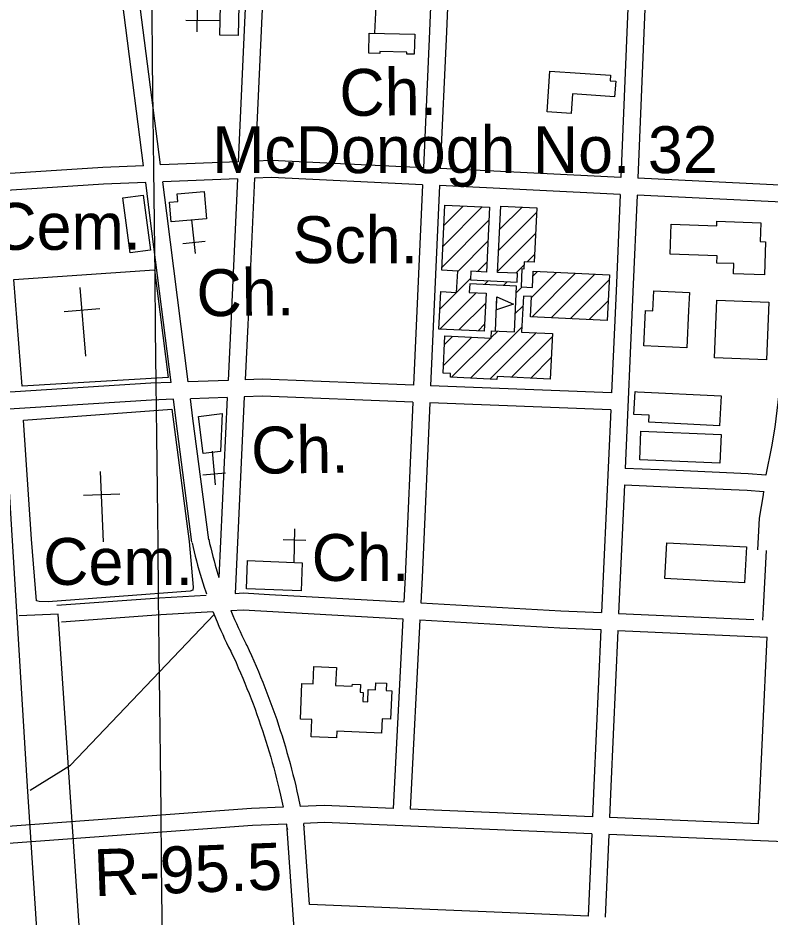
# Model space of a CAD drawing. Extents: x 3677843 to 3715951, y 511991 to 537744.
# Drawn here: x 3687026 to 3688357, y 526272 to 527864 of the extents above; entities that cross this region are included whole.
import ezdxf

# ---------------------------------------------------------------- set-up
doc = ezdxf.new("R2010")
doc.units = 0
for name, color, linetype in [('V-BLDG-IDEN', 7, 'Continuous'), ('V-BLDG-OTLN', 7, 'Continuous'), ('V-GRID-MAJR', 7, 'Continuous'), ('V-RIVR-RANG-IDEN', 7, 'Continuous'), ('V-ROAD-CNTR', 7, 'Continuous'), ('V-SITE-OTLN', 7, 'Continuous'), ('V-SITE-OTLN-IDEN', 7, 'Continuous')]:
    doc.layers.add(name, color=color, linetype=linetype)

msp = doc.modelspace()

# ---------------------------------------------------------------- linework, layer by layer
at = {"layer": 'V-BLDG-OTLN'}
for p, q in [((3687778.4752784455, 527459.874870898), (3687847.7878484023, 527529.1874408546)), ((3687780.2604947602, 527497.015426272), (3687814.0541724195, 527530.8091039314)), ((3687876.864537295, 527452.1981125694), (3687943.984850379, 527519.3184256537)), ((3687878.6501828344, 527489.339097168), (3687918.3094837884, 527528.9983981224)), ((3687776.690062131, 527422.7343155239), (3687859.613205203, 527505.6574585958)), ((3687804.3940204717, 527415.0829348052), (3687857.8268622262, 527468.5157765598)), ((3687875.078891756, 527415.057127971), (3687942.1988848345, 527482.1771210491)), ((3687927.2875798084, 527431.9104769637), (3687940.4129192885, 527445.0358164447)), ((3687839.327857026, 527414.6614323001), (3687856.04051925, 527431.3740945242)), ((3687907.16133071, 527411.7842278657), (3687921.991344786, 527426.6142419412)), ((3687935.1778677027, 527369.09008674), (3687979.387713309, 527413.2999323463)), ((3687936.0287458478, 527334.5856258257), (3688013.1207060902, 527411.6775860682)), ((3687937.582053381, 527406.8496114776), (3687945.6547205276, 527414.922278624)), ((3687969.762257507, 527332.9637984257), (3688046.8536988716, 527410.0552397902)), ((3687802.608089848, 527377.9416651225), (3687826.990631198, 527402.3242064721)), ((3687851.625244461, 527391.603480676), (3687858.484113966, 527398.4623501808)), ((3687885.358267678, 527389.9811648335), (3687892.217521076, 527396.8404182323)), ((3688003.4957691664, 527331.3419710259), (3688072.396078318, 527400.2422801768)), ((3687772.875313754, 527348.2088890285), (3687802.5864146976, 527377.9199899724)), ((3687772.986086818, 527312.9643230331), (3687837.128189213, 527377.1064254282)), ((3687908.097118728, 527377.3646768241), (3687918.292884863, 527387.5604429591)), ((3687806.7180800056, 527311.3409771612), (3687853.867621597, 527358.4905187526)), ((3687871.396575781, 527309.963218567), (3687873.7355711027, 527369.9170986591)), ((3688037.2292808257, 527329.720143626), (3688070.609743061, 527363.1006058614)), ((3687906.310906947, 527340.2231259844), (3687919.782329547, 527353.6945485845)), ((3687827.3458372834, 527225.9027172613), (3687917.9956583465, 527316.5525383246)), ((3687840.450073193, 527309.7176312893), (3687852.0818306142, 527321.3493887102)), ((3687863.9145900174, 527297.8268090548), (3687875.4122137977, 527309.3244328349)), ((3687779.2358858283, 527248.5034439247), (3687829.1952836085, 527298.4628417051)), ((3687781.0219190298, 527285.6448161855), (3687795.461775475, 527300.0846726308)), ((3687793.6122612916, 527227.5244803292), (3687862.9287917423, 527296.8410107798)), ((3687861.0794132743, 527224.2809541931), (3687943.2467605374, 527306.4483014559)), ((3687899.8535028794, 527227.6997047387), (3687971.642557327, 527299.4887591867)), ((3687933.586616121, 527226.0774789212), (3687969.8561386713, 527262.3470014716)), ((3687967.3197293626, 527224.4552531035), (3687968.0697200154, 527225.2052437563))]:
    msp.add_line(p, q, dxfattribs=at)
for points in [[(3687383.756, 527833.48), (3687386.173, 527940.468), (3687418.228, 527939.745), (3687415.807, 527832.755)], [(3687647.903, 527836.958), (3687728.529, 527834.987), (3687727.662, 527799.426), (3687714.43, 527799.748), (3687714.5160000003, 527803.203), (3687666.614, 527804.372), (3687666.522, 527800.604), (3687647.025, 527801.085)], [(3688007.518, 527729.1630000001), (3688005.144, 527694.626), (3687962.582, 527697.552), (3687967.534, 527769.601), (3688075.1040000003, 527762.208), (3688074.4280000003, 527752.373), (3688084.058, 527751.712), (3688082.1550000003, 527724.033)], [(3687248.193, 527549.808), (3687260.958, 527452.693), (3687224.895, 527447.952), (3687212.128, 527545.066)], [(3687355.785, 527556.425), (3687359.737, 527507.844), (3687297.615, 527502.792), (3687294.771, 527537.759), (3687309.348, 527538.9450000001), (3687308.259, 527552.558)], [(3687851.497, 527309.186), (3687771.185, 527313.051), (3687774.369, 527379.277), (3687802.6070000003, 527377.919), (3687804.426, 527415.748), (3687776.419, 527417.095), (3687781.9590000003, 527532.352), (3687860.715, 527528.566), (3687855.2, 527413.898), (3687827.611, 527415.225), (3687826.878, 527399.982), (3687909.468, 527396.011), (3687910.219, 527411.637), (3687874.9960000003, 527413.333), (3687880.644, 527530.81), (3687944.39, 527527.7440000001), (3687939.753, 527431.312), (3687922.257, 527432.152), (3687921.6350000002, 527419.186), (3687918.02, 527419.358), (3687916.4960000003, 527387.647), (3687936.612, 527386.678), (3687937.988, 527415.291), (3688072.808, 527408.807), (3688068.931, 527328.196), (3687933.525, 527334.706), (3687935.238, 527370.341), (3687920.617, 527371.046), (3687917.569, 527307.683), (3687971.911, 527305.0700000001), (3687968.032, 527224.421), (3687874, 527228.943), (3687873.7460000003, 527223.672), (3687791.667, 527227.618), (3687791.9820000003, 527234.2170000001), (3687778.58, 527234.8640000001), (3687781.748, 527300.7440000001), (3687863.865, 527296.796), (3687864.4930000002, 527309.85), (3687904.757, 527307.912), (3687908.65, 527388.861), (3687825.727, 527392.849), (3687824.998, 527377.6900000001), (3687854.722, 527376.26)], [(3688182.033597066, 527498.500976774), (3688262.6984357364, 527495.84298209), (3688262.9614352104, 527503.82796612), (3688340.835279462, 527501.2689712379), (3688339.735281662, 527467.8000381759), (3688349.15626282, 527467.490038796), (3688347.232266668, 527408.8621560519), (3688292.704375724, 527410.651152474), (3688293.2993745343, 527428.7711162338), (3688262.9734351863, 527429.766114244), (3688263.3954343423, 527442.6280885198), (3688180.2866005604, 527445.35808306)], [(3688213.0235350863, 527346.0432816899), (3688209.8095415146, 527279.5784146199), (3688133.7416936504, 527283.256407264), (3688136.760687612, 527345.6882823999), (3688149.962661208, 527345.0502836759), (3688151.679657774, 527380.574212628), (3688214.545532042, 527377.5352187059)], [(3687873.7355711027, 527369.9170986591), (3687903.2625120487, 527357.2061240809), (3687872.8345729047, 527346.8331448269)], [(3688262.9794351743, 527364.3722450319), (3688354.897251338, 527360.6622524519), (3688350.7752595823, 527258.544456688), (3688258.857443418, 527262.2554492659)], [(3688122.730715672, 527202.1185695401), (3688270.3714203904, 527194.7755842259), (3688267.742425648, 527141.8906899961), (3688142.422676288, 527148.1236775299), (3688143.045675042, 527160.6656524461), (3688116.229728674, 527161.9986497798), (3688118.2337246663, 527202.3405690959)], [(3687354.109, 527092.436), (3687345.819, 527158.339), (3687387.893, 527163.631), (3687384.913, 527096.311)], [(3688128.653703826, 527132.4207089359), (3688270.6184198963, 527126.270721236), (3688268.4094243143, 527075.2738232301), (3688126.4457082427, 527081.4218109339)], [(3688174.548612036, 526934.697104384), (3688315.534330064, 526927.1671194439), (3688312.155336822, 526863.8972459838), (3688171.169618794, 526871.4272309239)], [(3687432.5500000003, 526903.367), (3687529.285, 526899.387), (3687527.225, 526849.326), (3687430.49, 526853.303)], [(3687526.2970000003, 526622.514), (3687528.9450000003, 526685.654), (3687548.622, 526684.827), (3687549.912, 526715.567), (3687589.7600000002, 526713.898), (3687588.421, 526681.959), (3687617.992, 526680.72), (3687618.154, 526684.558), (3687632.562, 526683.954), (3687631.98, 526670.056), (3687637.002, 526669.848), (3687636.322, 526653.65), (3687645.392, 526653.269), (3687646.298, 526674.828), (3687659.198, 526674.2880000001), (3687659.722, 526686.8150000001), (3687678.275, 526686.039), (3687677.724, 526672.95), (3687687.622, 526672.535), (3687685.519, 526622.359), (3687670.9, 526622.973), (3687669.833, 526597.574), (3687590.7600000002, 526600.8910000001), (3687590.264, 526589.062), (3687545.061, 526590.961), (3687546.349, 526621.672)]]:
    msp.add_lwpolyline(points, close=True, dxfattribs=at)
at = {"layer": 'V-GRID-MAJR'}
msp.add_spline([(3687380.148, 517465.955), (3687312.292, 523524.615), (3687244.413, 529585.207), (3687176.535, 535645.813), (3687176.514, 535647.732)], degree=3, dxfattribs=at)
at = {"layer": 'V-ROAD-CNTR'}
for points in [[(3687104.4407522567, 525566.6258405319), (3687043.284874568, 526503.0999675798), (3686990.7459796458, 527354.055265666), (3686873.902213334, 529100.4247729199)], [(3687450.289060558, 528352.4712688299), (3687427.876105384, 527868.1422374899), (3687416.0471290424, 527609.10275557)], [(3687480.3130005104, 528352.295269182), (3687457.8440454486, 527866.7642402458), (3687446.135068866, 527610.3467530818)], [(3687248.65846382, 527602.1817694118), (3687154.515652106, 528335.5063027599)], [(3687278.745403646, 527603.4257669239), (3687184.492592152, 528337.6062985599)], [(3687775.275410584, 528340.3552930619), (3687754.52745208, 527840.2212933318), (3687743.7084737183, 527598.4047769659)], [(3687805.244350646, 528338.9702958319), (3687784.499392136, 527838.9292959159), (3687773.673413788, 527596.9407798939)], [(3688123.8257134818, 528324.2563252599), (3688092.984775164, 527581.329811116)], [(3688153.7946535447, 528322.872328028), (3688122.949715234, 527579.864814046)], [(3687743.7094737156, 527598.4047769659), (3687475.026011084, 527611.5397506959), (3687446.136068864, 527610.3457530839)], [(3687248.659463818, 527602.18276941), (3687176.290608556, 527599.1917753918), (3686225.6675098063, 527537.429898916)], [(3687416.04812904, 527609.1017555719), (3687278.7464036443, 527603.426766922)], [(3688092.985775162, 527581.3288111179), (3687773.674413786, 527596.939779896)], [(3687414.6751317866, 527579.0198157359), (3687282.5793959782, 527573.5598266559)], [(3687414.6741317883, 527579.0208157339), (3687402.9411552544, 527322.0803296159), (3687398.212164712, 527222.0775296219)], [(3687444.7620716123, 527580.264813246), (3687432.909095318, 527320.6883323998), (3687428.2961045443, 527223.126527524)], [(3687742.3684763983, 527568.4338369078), (3687474.912011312, 527581.509810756), (3687444.7620716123, 527580.2638132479)], [(3688386.98118717, 527566.955839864), (3688122.949715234, 527579.8638140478)], [(3687252.49345615, 527572.315829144), (3687177.8826053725, 527569.2318353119), (3686227.667505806, 527507.496958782)], [(3687297.6463658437, 527218.5735366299), (3687259.965441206, 527514.10794556), (3687252.49345615, 527572.3148291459)], [(3687327.755305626, 527219.621534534), (3687289.72338169, 527517.915937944), (3687282.5793959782, 527573.5588266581)], [(3687742.3684763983, 527568.4348369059), (3687726.4955081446, 527213.6525464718)], [(3687772.33241647, 527566.970839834), (3687756.4724481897, 527212.4695488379)], [(3688091.74177765, 527551.353871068), (3687772.33241647, 527566.968839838)], [(3688091.740777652, 527551.3548710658), (3688084.629791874, 527380.062213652), (3688076.5628080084, 527199.8365741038)], [(3688121.705717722, 527549.889873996), (3688114.60173193, 527378.7702162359), (3688100.618039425, 527066.348278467)], [(3688390.1515693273, 527536.7650711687), (3688121.705717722, 527549.888873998)], [(3688389.225626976, 527536.6544110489), (3688388.837450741, 527526.5680364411), (3688376.3987918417, 527260.0106354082), (3688374.15144861, 527213.2494835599), (3688365.3986004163, 527139.3312702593), (3688359.6773013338, 527104.2242377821), (3688349.865151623, 527054.6823540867), (3688349.811977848, 527054.3199031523)], [(3687297.647365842, 527218.5735366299), (3687261.2584386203, 527217.305539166), (3686494.577971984, 527168.4686368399), (3686251.6424578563, 527148.737676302)], [(3687398.21316471, 527222.0775296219), (3687327.7563056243, 527219.6225345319)], [(3687726.496508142, 527213.6525464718), (3687459.1930427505, 527224.201525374), (3687428.2961045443, 527223.1255275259)], [(3688076.5638080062, 527199.8365741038), (3687756.4724481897, 527212.4695488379)], [(3687301.457358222, 527188.6885964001), (3687262.734435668, 527187.339599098), (3686496.745967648, 527138.5466966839), (3686253.643453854, 527118.8007361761)], [(3687334.3052925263, 526935.7981021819), (3687306.315348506, 527150.5816726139), (3687301.457358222, 527188.6885964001)], [(3687396.791167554, 527192.0095897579), (3687331.5662980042, 527189.7375943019)], [(3687364.0532330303, 526939.6740944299), (3687336.0692889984, 527154.417664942), (3687331.5662980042, 527189.7365943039)], [(3687396.791167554, 527192.0105897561), (3687381.7191976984, 526873.2852272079)], [(3687426.8741073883, 527193.0585876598), (3687410.4131403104, 526844.9342839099)], [(3687725.1565108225, 527183.6816064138), (3687459.1230428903, 527194.181585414), (3687426.8741073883, 527193.057587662)], [(3687725.1545108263, 527183.682606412), (3687711.3205384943, 526874.4602248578), (3687709.0215430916, 526829.8473140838)], [(3687755.1314508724, 527182.499608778), (3687741.2864785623, 526873.0182277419), (3687738.9754831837, 526828.168317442)], [(3688075.22181069, 527169.8656340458), (3687755.1324508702, 527182.4986087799)], [(3688075.22181069, 527169.866634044), (3688059.1568428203, 526810.9463518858)], [(3688100.6099950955, 527066.9591555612), (3688191.2087240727, 527063.1179712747), (3688318.2799328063, 527057.5039893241), (3688349.930484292, 527055.0122210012)], [(3688099.3063326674, 527037.0422874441), (3688089.124782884, 526809.5673546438)], [(3688099.3392035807, 527036.9860828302), (3688189.9112759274, 527033.1460287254), (3688316.440067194, 527027.556010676), (3688345.547575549, 527025.2644497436)], [(3688345.637485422, 527025.8768361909), (3688344.6884591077, 527019.4129092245), (3688338.125380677, 526978.2309144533), (3688335.2070980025, 526921.9132320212)], [(3687334.54829204, 526934.4311049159), (3687336.330288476, 526926.5401206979), (3687338.2072847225, 526918.593136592), (3687340.1652808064, 526910.665152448), (3687342.2012767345, 526902.758168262), (3687344.316272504, 526894.871184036), (3687346.511268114, 526887.006199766), (3687348.782263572, 526879.1642154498), (3687351.132258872, 526871.343231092), (3687353.5612540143, 526863.5472466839), (3687356.067249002, 526855.775262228), (3687358.6502438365, 526848.0302777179), (3687359.9052413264, 526844.3872850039)], [(3687363.8102335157, 526941.041091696), (3687365.560230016, 526933.2941071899), (3687367.369226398, 526925.6391225), (3687369.255222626, 526918.0031377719), (3687371.217218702, 526910.3841530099), (3687373.254214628, 526902.7871682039), (3687375.367210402, 526895.2101833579), (3687381.7191976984, 526873.2852272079)], [(3688350.187, 526921.137), (3688344.733, 526818.811), (3688343.721561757, 526797.8563389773)], [(3687094.886771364, 526823.9243259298), (3687277.0194070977, 526837.425298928), (3687359.5262420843, 526842.0692896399)], [(3687410.4131403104, 526844.9342839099), (3687425.140110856, 526845.7632822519), (3687471.4260182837, 526843.168287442)], [(3687471.4260182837, 526843.168287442), (3687709.0215430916, 526829.8473140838)], [(3687403.1191548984, 526814.476344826), (3687425.1441108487, 526815.7153423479), (3687707.4775461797, 526799.8863740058)], [(3687738.974483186, 526828.1673174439), (3687986.7789875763, 526814.2743452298), (3688059.1568428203, 526810.945351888)], [(3687097.681765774, 526808.3393571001), (3687028.480904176, 526805.5713626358)], [(3687181.5465980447, 525565.8098421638), (3687097.681765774, 526808.3393571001)], [(3687103.221754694, 526794.4593848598), (3687278.9714031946, 526807.487358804), (3687371.39821834, 526812.6903483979)], [(3687119.18372277, 526540.8518920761), (3687373.8012135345, 526807.672358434)], [(3687371.39821834, 526812.6903483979), (3687378.879203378, 526794.5813846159), (3687382.072196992, 526787.067399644), (3687385.3391904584, 526779.5844146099), (3687388.6821837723, 526772.133429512), (3687392.09817694, 526764.7174443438), (3687395.5881699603, 526757.3354591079), (3687399.152162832, 526749.9884738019), (3687402.779155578, 526742.69948838), (3687404.0971529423, 526740.0924935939)], [(3687403.1191548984, 526814.476344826), (3687406.549148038, 526806.1753614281), (3687409.624141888, 526798.9353759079), (3687412.7731355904, 526791.726390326), (3687415.992129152, 526784.54940468), (3687419.284122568, 526777.405418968), (3687422.6461158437, 526770.2934331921), (3687426.0781089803, 526763.216447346), (3687429.5931019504, 526756.1514614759), (3687430.8670994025, 526753.6344665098)], [(3687707.4775461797, 526799.8873740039), (3687690.1835807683, 526464.2640452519)], [(3688089.124782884, 526809.566354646), (3688328.483710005, 526798.5571942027)], [(3687737.431486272, 526798.2073773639), (3687720.1575208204, 526463.0060477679)], [(3687737.430486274, 526798.2073773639), (3687985.250990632, 526784.312405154), (3688057.814845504, 526780.9754118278)], [(3688057.814845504, 526780.9764118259), (3688045.453870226, 526504.786964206), (3688043.053875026, 526449.4530748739)], [(3688087.783785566, 526779.5974145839), (3688075.423810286, 526503.466966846), (3688073.02681508, 526448.19507739)], [(3688087.7827855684, 526779.5964145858), (3688351.8122575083, 526767.452438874)], [(3688336.768287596, 526437.1240995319), (3688351.8122575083, 526767.452438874)], [(3687431.0830989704, 526753.188467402), (3687435.337090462, 526744.0414856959), (3687439.5410820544, 526734.8075041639), (3687443.67307379, 526725.540522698), (3687447.730065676, 526716.2385413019), (3687451.7130577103, 526706.9065599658), (3687455.6210498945, 526697.5425786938), (3687459.454042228, 526688.1475974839), (3687463.21303471, 526678.7216163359), (3687466.8950273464, 526669.267635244), (3687470.5020201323, 526659.783654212), (3687474.0340130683, 526650.2716732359), (3687477.4900061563, 526640.730692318), (3687480.8689993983, 526631.163711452), (3687484.17299279, 526621.5687306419), (3687487.398986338, 526611.9477498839), (3687490.5479800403, 526602.3027691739), (3687493.619973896, 526592.6327885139), (3687496.614967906, 526582.9368079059), (3687499.53296207, 526573.2198273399), (3687502.3729563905, 526563.477846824), (3687505.134950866, 526553.7148663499), (3687507.818945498, 526543.928885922), (3687510.424940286, 526534.1219055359), (3687512.9529352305, 526524.2959251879), (3687515.4029303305, 526514.4489448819), (3687517.773925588, 526504.5819646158), (3687520.064921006, 526494.696984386), (3687522.2779165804, 526484.79500419), (3687525.9529092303, 526467.7110383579)], [(3687403.8811533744, 526740.5384927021), (3687408.0831449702, 526731.5015107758), (3687412.189136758, 526722.483528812), (3687416.22312869, 526713.4345469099), (3687420.184120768, 526704.3545650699), (3687424.0731129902, 526695.240583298), (3687427.889105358, 526686.0986015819), (3687431.632097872, 526676.9256199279), (3687435.3010905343, 526667.721638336), (3687438.897083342, 526658.4896568), (3687442.4200762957, 526649.22967532), (3687445.8680694, 526639.9416938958), (3687449.242062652, 526630.6267125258), (3687452.5430560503, 526621.2837312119), (3687455.7670496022, 526611.9167499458), (3687458.917043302, 526602.5237687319), (3687461.9920371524, 526593.10478757), (3687464.992031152, 526583.662806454), (3687467.917025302, 526574.1968253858), (3687470.7650196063, 526564.707844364), (3687473.539014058, 526555.1958633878), (3687476.2350086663, 526545.6628824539), (3687478.857003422, 526536.1089015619), (3687481.400998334, 526526.533920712), (3687483.8689933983, 526516.9379399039), (3687486.260988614, 526507.3229591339), (3687488.575983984, 526497.6899784), (3687490.8129795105, 526488.038997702), (3687495.6209698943, 526466.5230407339)], [(3687047.8578654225, 526496.9349799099), (3687119.18372277, 526540.8518920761)], [(3687495.6209698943, 526466.5230407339), (3687439.7170817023, 526464.3330451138), (3686304.6933517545, 526380.376213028)], [(3687690.1835807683, 526464.263045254), (3687568.416824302, 526469.3740350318), (3687525.9529092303, 526467.7110383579)], [(3688043.053875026, 526449.4520748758), (3687720.1585208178, 526463.00504777)], [(3687502.3199564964, 526436.7621002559), (3687441.411078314, 526434.377105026), (3686306.769347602, 526350.4472728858)], [(3687527.1989067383, 526073.952825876), (3687502.3199564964, 526436.7621002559)], [(3688041.7538776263, 526419.4811348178), (3687568.374824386, 526439.3500950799), (3687532.309896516, 526437.9370979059)], [(3687542.16287681, 526294.2473852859), (3687532.309896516, 526437.9370979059)], [(3687532.4998961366, 526433.077107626), (3687532.5948959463, 526432.5381087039)], [(3688336.768287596, 526437.1240995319), (3688073.027815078, 526448.1940773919)], [(3687502.714955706, 526429.232115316), (3687503.05295503, 526427.32011914)], [(3688041.7538776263, 526419.4811348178), (3688035.4198902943, 526273.4394269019)], [(3688071.727817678, 526418.2231373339), (3688065.39183035, 526272.1244295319)], [(3688495.1029709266, 526400.4521728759), (3688071.727817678, 526418.222137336)], [(3687925.549110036, 526278.132417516), (3687542.16287681, 526294.248385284)], [(3688035.420890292, 526273.4394269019), (3687995.48697016, 526275.1924233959), (3687925.549110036, 526278.132417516)]]:
    msp.add_lwpolyline(points, dxfattribs=at)
at = {"layer": 'V-SITE-OTLN'}
for p, q in [((3687657.842279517, 527837.1997536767), (3687660.5552740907, 527897.1386337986)), ((3687343.4768879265, 527879.099265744), (3687342.848889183, 527839.1043457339)), ((3687383.1578085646, 527858.4733069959), (3687323.164928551, 527859.41630511)), ((3687333.6813719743, 527506.409567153), (3687339.8554064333, 527446.728234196)), ((3687317.903660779, 527464.5643308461), (3687357.6915030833, 527468.6799798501)), ((3687146.176668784, 527265.19344339), (3687136.4116883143, 527386.777200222)), ((3687171.0716189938, 527348.776276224), (3687108.2487446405, 527343.7302863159)), ((3687370.0426552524, 527096.7214802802), (3687375.0682398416, 527036.9327416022)), ((3687177.8216054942, 526936.190101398), (3687172.644615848, 527060.9748518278)), ((3687353.463429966, 527055.1864605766), (3687393.3229573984, 527058.5374982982)), ((3687206.601547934, 527020.7209323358), (3687142.125676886, 527018.045937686)), ((3687514.932868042, 526899.2619037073), (3687516.2738653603, 526959.2467837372)), ((3687535.8218262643, 526938.8048246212), (3687495.831906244, 526939.6988228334))]:
    msp.add_line(p, q, dxfattribs=at)
for points in [[(3687291.92, 527227.436), (3687033.79, 527211.873), (3687018.907, 527400.816), (3687268.122, 527417.66)], [(3687329.044, 526936.632), (3687336.257, 526856.062), (3687335.649, 526850.76), (3687330.926, 526849.009), (3687079.833, 526829.845), (3687063.924, 526830.491), (3687059.214, 526831.687), (3687050.166, 526940.732), (3687036.438, 527151.611), (3687298.639, 527171.325)]]:
    msp.add_lwpolyline(points, close=True, dxfattribs=at)

# ---------------------------------------------------------------- texts
at = {"layer": 'V-BLDG-IDEN'}
msp.add_text('Ch.', height=82.999832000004, rotation=0.6583499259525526, dxfattribs=at).set_placement((3687595.5037701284, 527689.9835938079))
for s, p in [('McDonogh No. 32', (3687369.842221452, 527589.005795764)), ('Sch.', (3687512.131936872, 527429.616114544))]:
    msp.add_text(s, height=82.99983200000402, dxfattribs=at).set_placement(p)
at = {"layer": 'V-RIVR-RANG-IDEN'}
msp.add_text('R-95.5', height=82.99999800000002, rotation=2.118194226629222, dxfattribs=at).set_placement((3687161.966, 526308.8470000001))
at = {"layer": 'V-SITE-OTLN-IDEN'}
for s, p in [('Cem.', (3686979.2375802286, 527453.2428429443)), ('Cem.', (3687071.0017332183, 526860.05368325)), ('Ch.', (3687546.0059798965, 526867.0522787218))]:
    msp.add_text(s, height=82.99983200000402, dxfattribs=at).set_placement(p)
for p in [(3687342.6692879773, 527335.4245213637), (3687439.244548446, 527056.792668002)]:
    msp.add_text('Ch.', height=82.999832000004, rotation=0.6583499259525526, dxfattribs=at).set_placement(p)

doc.saveas('drawing.dxf')
